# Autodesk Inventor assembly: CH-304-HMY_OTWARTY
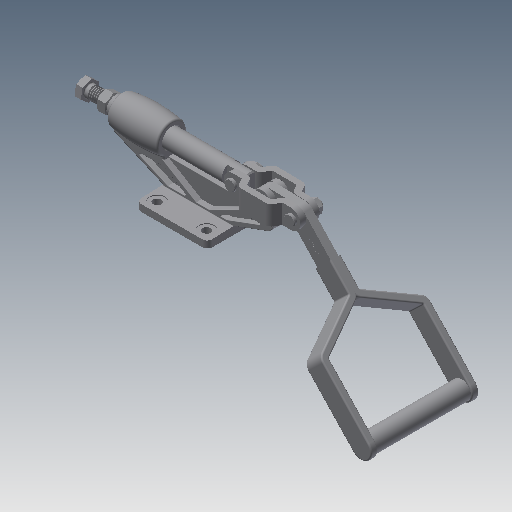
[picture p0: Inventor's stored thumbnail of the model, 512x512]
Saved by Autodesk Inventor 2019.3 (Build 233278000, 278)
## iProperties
Company: Î¢ÈíÖÐ¹ú
Created: 2015-08
Part Number: CH-304-HMY_OTWARTY
Material: Ogólny
Description: STEP AP203
Document SubType Name: Assembly
Designer: CADENGINEERING4
Sending System: SolidWorks 2012
Preprocessor: SwSTEP 2.0
Title: CH-304-HMY.STEP
Author: Î¢ÈíÓÃ»§
Revision Number: ÈÎºÎ
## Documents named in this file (12)
- D:\Vault_2016\Projekty\STRONA\Push-pull clamp\CH-304-HMY\CH-304-HMY_OTWARTY.iam
- D:\Vault_2016\Projekty\STRONA\Push-pull clamp\CH-304-HMY\CH-304-HM-01 BASE.ipt
- D:\Vault_2016\Projekty\STRONA\Push-pull clamp\CH-304-HMY\CH-304-HM-02 CREST STALK.ipt
- D:\Vault_2016\Projekty\STRONA\Push-pull clamp\CH-304-HMY\CH-304-HM-07.ipt
- D:\Vault_2016\Projekty\STRONA\Push-pull clamp\CH-304-HMY\CH-304-HM-04 CONNECTING-PLATE.ipt
- D:\Vault_2016\Projekty\STRONA\Push-pull clamp\CH-304-HMY\304-05.ipt
- D:\Vault_2016\Projekty\STRONA\Push-pull clamp\CH-304-HMY\5-16 LOCK NUT.ipt
- D:\Vault_2016\Projekty\STRONA\Push-pull clamp\CH-304-HMY\CH-304-HM-06.ipt
- D:\Vault_2016\Projekty\STRONA\Push-pull clamp\CH-304-HMY\M12 Nut.ipt
- D:\Vault_2016\Projekty\STRONA\Push-pull clamp\CH-304-HMY\CH-SA-125017 SPINDLE SUPPLIED.ipt
- D:\Vault_2016\Projekty\STRONA\Push-pull clamp\CH-304-HMY\CH-304-HMY-SHOUBA.ipt
- D:\Vault_2016\Projekty\STRONA\Push-pull clamp\CH-304-HMY\CH-304-HMY-06.ipt
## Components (15 placed, 15 different names)
1. CH-304-HM-01 BASE_1 — Zestawiające:10, Zestawiające:12, Zestawiające:22, Zestawiające:23, Zestawiające:24, Zestawiające:27
2. CH-304-HM-02 CREST STALK_2 — Zestawiające:3, Zestawiające:4, Zestawiające:17, Zestawiające:24
3. CH-304-HM-07_3 — Zestawiające:11, Zestawiające:12, Równoległe:3
4. CH-304-HM-07_4 — Zestawiające:14
5. CH-304-HM-04 CONNECTING-PLATE_5 — Równoległe:1, Równoległe:2, Zestawiające:8, Zestawiające:9, Zestawiające:15, Zestawiające:16, Zestawiające:26
6. CH-304-HM-04 CONNECTING-PLATE_6 — Zestawiające:13, Zestawiające:14, Zestawiające:15, Zestawiające:17, Zestawiające:18, Zestawiające:19, Zestawiające:20, Zestawiające:21
7. 304-05_7 — Zestawiające:22, Zestawiające:23
8. 5-16 LOCK NUT_8 — Równoległe:2, Zestawiające:9
9. CH-304-HM-06_9 — Zestawiające:20, Zestawiające:21
10. CH-304-HM-06_10 — Zestawiające:18, Zestawiające:19, Zestawiające:25, Zestawiające:26
11. 5-16 LOCK NUT_11 — Równoległe:1, Zestawiające:8
12. M12 Nut_12 — Zestawiające:1, Zestawiające:2, Zestawiające:3
13. CH-SA-125017 SPINDLE SUPPLIED_13 — Zestawiające:1, Zestawiające:2, Zestawiające:4
14. CH-304-HMY-SHOUBA_14 — Zestawiające:5, Zestawiające:6, Zestawiające:7, Zestawiające:10, Zestawiające:11, Równoległe:3, Zestawiające:13, Zestawiające:16, Zestawiające:25, Zestawiające:27
15. CH-304-HMY-06_15 — Zestawiające:5, Zestawiające:6, Zestawiające:7
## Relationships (30: Mate 27, Flush 3)
- Zestawiające:1 [Mate]: M12 Nut_12 ↔ CH-SA-125017 SPINDLE SUPPLIED_13
- Zestawiające:2 [Mate]: M12 Nut_12 ↔ CH-SA-125017 SPINDLE SUPPLIED_13
- Zestawiające:3 [Mate]: CH-304-HM-02 CREST STALK_2 ↔ M12 Nut_12
- Zestawiające:4 [Mate]: CH-304-HM-02 CREST STALK_2 ↔ CH-SA-125017 SPINDLE SUPPLIED_13
- Zestawiające:5 [Mate]: CH-304-HMY-SHOUBA_14 ↔ CH-304-HMY-06_15
- Zestawiające:6 [Mate]: CH-304-HMY-SHOUBA_14 ↔ CH-304-HMY-06_15
- Zestawiające:7 [Mate]: CH-304-HMY-SHOUBA_14 ↔ CH-304-HMY-06_15
- Równoległe:1 [Flush]: CH-304-HM-04 CONNECTING-PLATE_5 ↔ 5-16 LOCK NUT_11
- Równoległe:2 [Flush]: CH-304-HM-04 CONNECTING-PLATE_5 ↔ 5-16 LOCK NUT_8
- Zestawiające:8 [Mate]: CH-304-HM-04 CONNECTING-PLATE_5 ↔ 5-16 LOCK NUT_11
- Zestawiające:9 [Mate]: CH-304-HM-04 CONNECTING-PLATE_5 ↔ 5-16 LOCK NUT_8
- Zestawiające:10 [Mate]: CH-304-HM-01 BASE_1 ↔ CH-304-HMY-SHOUBA_14
- Zestawiające:11 [Mate]: CH-304-HM-07_3 ↔ CH-304-HMY-SHOUBA_14
- Zestawiające:12 [Mate]: CH-304-HM-01 BASE_1 ↔ CH-304-HM-07_3
- Równoległe:3 [Flush]: CH-304-HM-07_3 ↔ CH-304-HMY-SHOUBA_14
- Zestawiające:13 [Mate]: CH-304-HM-04 CONNECTING-PLATE_6 ↔ CH-304-HMY-SHOUBA_14
- Zestawiające:14 [Mate]: CH-304-HM-07_4 ↔ CH-304-HM-04 CONNECTING-PLATE_6
- Zestawiające:15 [Mate]: CH-304-HM-04 CONNECTING-PLATE_5 ↔ CH-304-HM-04 CONNECTING-PLATE_6
- Zestawiające:16 [Mate]: CH-304-HM-04 CONNECTING-PLATE_5 ↔ CH-304-HMY-SHOUBA_14
- Zestawiające:17 [Mate]: CH-304-HM-02 CREST STALK_2 ↔ CH-304-HM-04 CONNECTING-PLATE_6
- Zestawiające:18 [Mate]: CH-304-HM-04 CONNECTING-PLATE_6 ↔ CH-304-HM-06_10
- Zestawiające:19 [Mate]: CH-304-HM-04 CONNECTING-PLATE_6 ↔ CH-304-HM-06_10
- Zestawiające:20 [Mate]: CH-304-HM-04 CONNECTING-PLATE_6 ↔ CH-304-HM-06_9
- Zestawiające:21 [Mate]: CH-304-HM-04 CONNECTING-PLATE_6 ↔ CH-304-HM-06_9
- Zestawiające:22 [Mate]: CH-304-HM-01 BASE_1 ↔ 304-05_7
- Zestawiające:23 [Mate]: CH-304-HM-01 BASE_1 ↔ 304-05_7
- Zestawiające:24 [Mate]: CH-304-HM-01 BASE_1 ↔ CH-304-HM-02 CREST STALK_2
- Zestawiające:25 [Mate]: CH-304-HM-06_10 ↔ CH-304-HMY-SHOUBA_14
- Zestawiające:26 [Mate]: CH-304-HM-04 CONNECTING-PLATE_5 ↔ CH-304-HM-06_10
- Zestawiające:27 [Mate]: CH-304-HM-01 BASE_1 ↔ CH-304-HMY-SHOUBA_14
